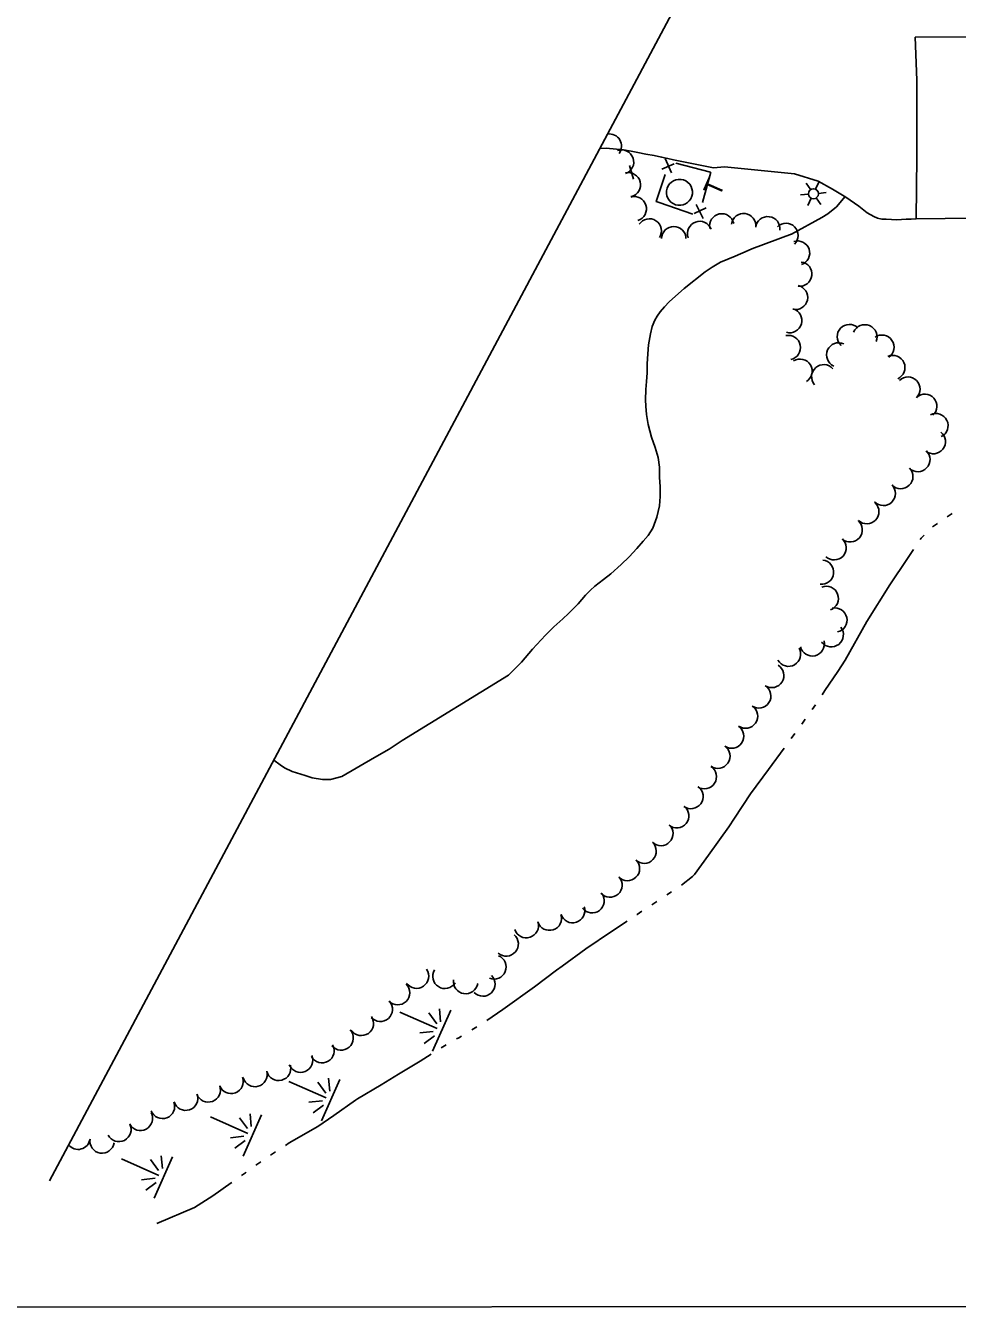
# Model space of a CAD drawing. Extents: x 189384 to 193282, y 256970 to 260388.
# Drawn here: x 189721.3 to 190027.6, y 257510.7 to 257932.1 of the extents above; entities that cross this region are included whole.
import ezdxf

# ---------------------------------------------------------------- set-up
doc = ezdxf.new("R2010")
doc.units = 0
for name, color, linetype in [('E_BLD', 7, 'Continuous'), ('E_BLD_Name', 7, 'Continuous'), ('E_DWY', 7, 'Continuous'), ('E_LAND_Vegetation', 7, 'Continuous'), ('E_MAP_GridLines', 7, 'Continuous'), ('E_MAP_Limits', 7, 'Continuous'), ('E_MISCPROP', 7, 'Continuous'), ('E_MISCPROP_Railing', 7, 'Continuous'), ('E_PATH_Sidewalk', 7, 'Continuous'), ('E_WTR', 7, 'Continuous')]:
    doc.layers.add(name, color=color, linetype=linetype)

# ---------------------------------------------------------------- blocks, each defined once
blk = doc.blocks.new('LTP_1')
at = {"layer": 'E_MISCPROP'}
for p, q in [((-1.61, 0.09), (-4.22, 0.17)), ((-0.78, 1.46), (-1.98, 3.76)), ((0.86, 1.37), (2.22, 3.6)), ((1.66, 0), (4.18, -0.07)), ((-0.86, -1.4), (-2.22, -3.59)), ((0.78, -1.44), (2.02, -3.62))]:
    blk.add_line(p, q, dxfattribs=at)
blk.add_circle((0.02, 0.01), 1.64, dxfattribs=at)
blk = doc.blocks.new('TA')
at = {"layer": 'E_BLD_Name'}
blk.add_text('T', height=6, rotation=0, dxfattribs=at).set_placement((-1.9, 0.03))
blk = doc.blocks.new('MARSH')
at = {"layer": 'E_WTR'}
for p, q in [((0.03, 15.02), (0.03, 1.6)), ((-1.34, 2.37), (-3.54, 6.22)), ((1.46, 2.37), (3.66, 6.22)), ((-6.13, 3.53), (-2.44, 1.44)), ((6.25, 3.53), (2.56, 1.44)), ((-7.39, -0.05), (7.4, -0.05))]:
    blk.add_line(p, q, dxfattribs=at)

msp = doc.modelspace()

# ---------------------------------------------------------------- linework, layer by layer
at = {"layer": 'E_BLD'}
msp.add_ellipse((189936.26, 257877.29), major_axis=(-4.07, 1.32), ratio=0.999619, dxfattribs=at)
at = {"layer": 'E_DWY'}
for points in [[(189910.06, 257891.68), (189912.2, 257891.77), (189917.92, 257891.22), (189920.42, 257890.81), (189922.62, 257890.35), (189925.22, 257889.79), (189927.98, 257889.38), (189930.37, 257888.86), (189932.46, 257888.36), (189934.35, 257887.94), (189947.43, 257885.35)], [(189947.43, 257885.35), (189951.04, 257885.61), (189974.13, 257883.38), (189981.84, 257880.95), (189986.61, 257878.37), (189991, 257875.72), (189995.23, 257872.75), (189997.97, 257870.59), (190000.14, 257869.37), (190001.41, 257868.75), (190002.77, 257868.5), (190004.26, 257868.41), (190006, 257868.32), (190007.57, 257868.2), (190009.27, 257868.31), (190010.81, 257868.47), (190012.46, 257868.44), (190014.02, 257868.62)], [(189990.7, 257875.9), (189987.88, 257872.49), (189985.08, 257870.23), (189983.1, 257868.99), (189973.05, 257863.5)], [(189937.83, 257845.65), (189944.7, 257851.11), (189946.97, 257852.64), (189949.77, 257854.33), (189952.14, 257855.3), (189954.62, 257856.25), (189958.87, 257858.18), (189960.02, 257858.67), (189973.33, 257863.65)], [(189937.83, 257845.65), (189935, 257843.18), (189932.85, 257841.24), (189931.38, 257839.65), (189929.94, 257837.99), (189928.91, 257836.57), (189928.15, 257835.27), (189927.28, 257833.23), (189926.7, 257830.73), (189926.1, 257827.1), (189925.83, 257824.22), (189925.67, 257820.88), (189925.61, 257817.96), (189925.47, 257815.1), (189925.22, 257812.47), (189925.15, 257809.03), (189925.25, 257807.02), (189925.44, 257804.21), (189925.96, 257800.99), (189927.11, 257796.81), (189928.24, 257793.37), (189929.21, 257790.13), (189929.72, 257786.9), (189929.75, 257783.7), (189929.87, 257780.48), (189929.94, 257777.28), (189929.66, 257774.23), (189928.82, 257770.51), (189927.56, 257766.92), (189926.03, 257764.44), (189924.37, 257762.65), (189922.21, 257760.24), (189919.68, 257757.43), (189917.11, 257754.9), (189913.67, 257751.85), (189911.32, 257749.96), (189908.47, 257747.83), (189907, 257746.51), (189905.43, 257744.84), (189902.95, 257742), (189899.8, 257738.85), (189897.98, 257737.11), (189894.95, 257734.41), (189892.24, 257731.74), (189890.77, 257730.15), (189888, 257727.11), (189884.34, 257722.84), (189880.1, 257718.58), (189845.14, 257697.05), (189840.86, 257694.25), (189836, 257691.49), (189825.24, 257685.23), (189821.57, 257684.21), (189818.98, 257684.27), (189815.57, 257684.77), (189813.2, 257685.61), (189809.01, 257686.9), (189806.45, 257688.05), (189805.06, 257689.04), (189802.88, 257690.62)]]:
    msp.add_lwpolyline(points, dxfattribs=at)
at = {"layer": 'E_LAND_Vegetation'}
msp.add_line((189921.18, 257881.56), (189919.83, 257886.14), dxfattribs=at)
for centre, start, end in [((189913.23, 257892.49), 322.8141, 99.0874), ((189917.23, 257887.23), 289.4175, 109.4022), ((189919.47, 257879.77), 283.9538, 103.9385), ((189921.41, 257871.9), 287.0173, 107.002), ((189926.35, 257864.59), 326.777, 146.7617), ((189950.17, 257866.26), 11.8181, 191.8028), ((189957.35, 257866.34), 352.5717, 172.5564), ((189965.28, 257865.31), 352.5717, 172.5564), ((189934.41, 257862.07), 359.9741, 179.9588), ((189942.91, 257863.76), 20.3311, 200.3158), ((189971.28, 257863.13), 314.8321, 134.8168), ((189975.09, 257857.31), 288.708, 108.6926), ((189975.8, 257850.41), 262.8336, 82.8183), ((189974.41, 257842.74), 257.669, 77.6537), ((189972.51, 257835.11), 254.1275, 74.1122), ((189992.12, 257829.87), 46.5686, 226.5533), ((189997.21, 257829.77), 337.0546, 157.0393), ((189972.06, 257826.26), 281.6786, 101.6632), ((189988.61, 257823.83), 65.8672, 245.8518), ((190002.81, 257826.37), 304.245, 124.2297), ((189975.88, 257818.49), 301.596, 121.5807), ((190006.39, 257819.69), 293.6822, 113.6668), ((189983.7, 257816.66), 41.4046, 221.3893), ((190011.36, 257812.59), 314.1957, 134.1804), ((190016.9, 257806.96), 311.7325, 131.7172), ((190020.56, 257800.56), 296.2088, 116.1934), ((190019.71, 257795.34), 231.5182, 51.5029), ((190014.63, 257789.45), 225.8891, 45.8738), ((190009.02, 257783.86), 223.7845, 43.7691), ((190003.26, 257778.31), 223.9602, 43.9449), ((189997.84, 257772.32), 226.3675, 46.3522), ((189992.38, 257766.33), 229.578, 49.5627), ((189987.1, 257760.43), 227.4177, 47.4024), ((189982.95, 257752.42), 263.7931, 83.7778), ((189984.51, 257743.79), 290.8987, 110.8834), ((189987.35, 257736.66), 282.6449, 102.6296), ((189986.16, 257731.85), 217.865, 37.8497), ((189979.9, 257728.84), 193.8888, 13.8735), ((189972.1, 257725.45), 210.095, 30.0797), ((189966.58, 257718.45), 238.1235, 58.1082), ((189962.33, 257711.72), 237.1016, 57.0862), ((189957.98, 257705.09), 235.1532, 55.1379), ((189953.42, 257698.52), 235.3035, 55.2882), ((189948.88, 257691.92), 235.8157, 55.8004), ((189944.44, 257685.2), 237.4375, 57.4222), ((189940.08, 257678.66), 233.7347, 53.7194), ((189935.34, 257672.33), 231.2286, 51.2133), ((189930.16, 257666.5), 226.1429, 46.1276), ((189924.63, 257660.68), 226.9208, 46.9055), ((189919.18, 257654.99), 223.8679, 43.8526), ((189913.44, 257649.56), 221.321, 41.3056), ((189907.53, 257644.39), 217.3802, 37.3648), ((189901.13, 257641.15), 198.033, 18.0176), ((189885.92, 257636.2), 198.033, 18.0176), ((189893.52, 257638.67), 198.033, 18.0176), ((189879.32, 257630.19), 229.2777, 49.2624), ((189875.31, 257622.64), 247.9124, 67.8971), ((189849.84, 257619.61), 214.6076, 34.5922), ((189859.16, 257619.55), 147.8958, 327.8805), ((189843.61, 257614.18), 224.6076, 44.5922), ((189865.99, 257617.82), 170.8812, 350.8658), ((189871.66, 257617.03), 224.0952, 44.0799), ((189837.94, 257608.71), 221.5138, 41.4985), ((189831.72, 257604.08), 215.0626, 35.0473), ((189825.04, 257599.31), 220.8923, 40.877), ((189818.78, 257595.12), 209.3076, 29.2923), ((189811.72, 257592), 202.1818, 22.1665), ((189788.89, 257585), 200.3346, 20.3193), ((189796.73, 257587.27), 195.7198, 15.7045), ((189804.5, 257589.3), 194.6573, 14.642), ((189781.38, 257582.21), 200.5017, 20.4864), ((189766.33, 257576.8), 200.7836, 20.7683), ((189773.97, 257579.49), 197.8489, 17.8336), ((189759.06, 257572.87), 208.4573, 28.442), ((189752.01, 257569.21), 207.0533, 27.038), ((189738.56, 257566.66), 219.1257, 351.1573), ((189746.46, 257565.43), 171.1727, 351.1573)]:
    msp.add_arc(centre, 4, start, end, dxfattribs=at)
at = {"layer": 'E_MAP_GridLines'}
msp.add_line((189647.76, 257510.74), (191647.75, 257512.16), dxfattribs=at)
at = {"layer": 'E_MAP_Limits'}
msp.add_lwpolyline([(190173.62, 258386.11), (189729.15, 257552.3)], dxfattribs=at)
at = {"layer": 'E_MISCPROP_Railing'}
for p, q in [((189930.48, 257884.92), (189934.5, 257886.65)), ((189933.62, 257883.71), (189931.62, 257888.41)), ((189941.81, 257873.3), (189944.02, 257868.69)), ((189944.99, 257872.23), (189941.06, 257870.31))]:
    msp.add_line(p, q, dxfattribs=at)
for points in [[(189935.12, 257886.92), (189946.46, 257883.95)], [(189929.54, 257873.92), (189928.63, 257874.23), (189931.53, 257883.13)], [(189946.61, 257883.92), (189943.86, 257873.97)], [(189940.63, 257870.09), (189929.54, 257873.92)]]:
    msp.add_lwpolyline(points, dxfattribs=at)
at = {"layer": 'E_PATH_Sidewalk'}
msp.add_lwpolyline([(190074.18, 257868.55), (190042.77, 257868.95), (190014.02, 257868.62), (190014.26, 257888.98), (190014.29, 257914.14), (190013.79, 257928.28), (190049.44, 257928.44), (190074.11, 257928.93), (190074.3, 257903.4)], dxfattribs=at)
at = {"layer": 'E_WTR'}
for points in [[(190024.31, 257770.59), (190025.92, 257771.68)], [(190019.46, 257767.32), (190021.08, 257768.41)], [(190015.39, 257763.13), (190015.68, 257763.56), (190016.69, 257764.57)], [(189997.88, 257736.17), (189997.91, 257736.22), (190005.41, 257748.24), (190011.24, 257756.93), (190013.22, 257759.9)], [(189983.13, 257712.09), (189984.08, 257713.5), (189988.37, 257719.8), (189990.76, 257723.53), (189997.88, 257736.17)], [(189979.85, 257707.25), (189980.94, 257708.86)], [(189976.48, 257702.47), (189977.63, 257704.05)], [(189973.03, 257697.76), (189974.18, 257699.33)], [(189954.38, 257671.57), (189959.63, 257679.52), (189965.54, 257687.56), (189970.72, 257694.61)], [(189936.93, 257649.57), (189940.57, 257652.4), (189941.2, 257652.99), (189945.84, 257659.44), (189952.51, 257668.74), (189954.38, 257671.57)], [(189932.07, 257646.32), (189933.7, 257647.39)], [(189922.3, 257639.9), (189922.34, 257639.93), (189923.92, 257640.97)], [(189927.18, 257643.11), (189928.81, 257644.18)], [(189895.9, 257621.54), (189897.74, 257622.92), (189905.53, 257628.59), (189913.94, 257634.25), (189919.07, 257637.71)], [(189872.95, 257605.06), (189878.18, 257608.64), (189888.6, 257616.08), (189895.9, 257621.54)], [(189867.99, 257601.97), (189869.65, 257602.99)], [(189862.98, 257598.96), (189863.76, 257599.36), (189864.67, 257599.92)], [(189857.93, 257596.02), (189858.45, 257596.35), (189859.59, 257597.03)], [(189830.47, 257579.29), (189838.24, 257583.9), (189843.9, 257587.44), (189850.99, 257591.71), (189854.62, 257593.97)], [(189806.75, 257563.99), (189808, 257564.82), (189817.4, 257570.22), (189822.63, 257573.78), (189829.81, 257578.9), (189830.47, 257579.29)], [(189801.87, 257560.75), (189803.5, 257561.83)], [(189797.05, 257557.45), (189798.65, 257558.57)], [(189792.27, 257554.08), (189793.58, 257555.01), (189793.86, 257555.21)], [(189764.44, 257538.31), (189776.82, 257543.53), (189782.92, 257547.39), (189788.94, 257551.72), (189789.09, 257551.83)]]:
    msp.add_lwpolyline(points, dxfattribs=at)

# ---------------------------------------------------------------- block references
at = {"layer": 'E_BLD_Name', "rotation": 66.26478215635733}
msp.add_blockref('TA', (189950.19, 257877.27), dxfattribs=at)
at = {"layer": 'E_MISCPROP', "rotation": 66.26478161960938}
msp.add_blockref('LTP_1', (189980.31, 257876.78), dxfattribs=at)
at = {"layer": 'E_WTR'}
for p, xscale, yscale, rotation in [((189858.04, 257601.69), 0.9999987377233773, 0.9999987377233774, 66.15393153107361), ((189821.59, 257578.89), 0.9999987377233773, 0.9999987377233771, 66.15393217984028), ((189795.81, 257567.23), 0.9999987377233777, 0.9999987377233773, 66.15393263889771), ((189766.59, 257553.44), 0.9999987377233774, 0.9999987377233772, 66.1539331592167)]:
    msp.add_blockref('MARSH', p, dxfattribs=dict(at, xscale=xscale, yscale=yscale, rotation=rotation))

doc.saveas('drawing.dxf')
